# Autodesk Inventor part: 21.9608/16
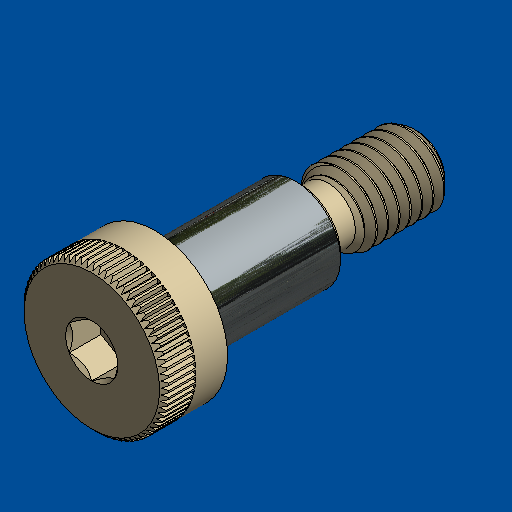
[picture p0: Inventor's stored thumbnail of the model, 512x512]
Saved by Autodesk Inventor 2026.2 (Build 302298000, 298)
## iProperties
Company: Managed by Terraform
Created: 2023-02
Part Number: 21.9608/16
Material: Steel
Description: SHOULD BOLT M8 16mm LONG
Document SubType Name: Modeling
Designer: amoles
Appearance: Beige
Stock Number: MC # 92981A302
Mass: 23.6454 g
Surface Area: 18.7616 cm^2
Volume: 3.01215 cm^3
Density: 7.85 g/cm^3
Vendor: S
Sending System: SolidWorks 2017
Preprocessor: SwSTEP 2.0
Title: 92981A302_Alloy Steel Shoulder Screws.STEP
Author: Administrator
Revision Number: ANY
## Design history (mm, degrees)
feature "CirPattern1"
body "Solid1"
